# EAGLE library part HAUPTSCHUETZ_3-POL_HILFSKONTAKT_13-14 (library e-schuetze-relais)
Hauptschütz 3-pol. mit Hilfskontakt-Schließer
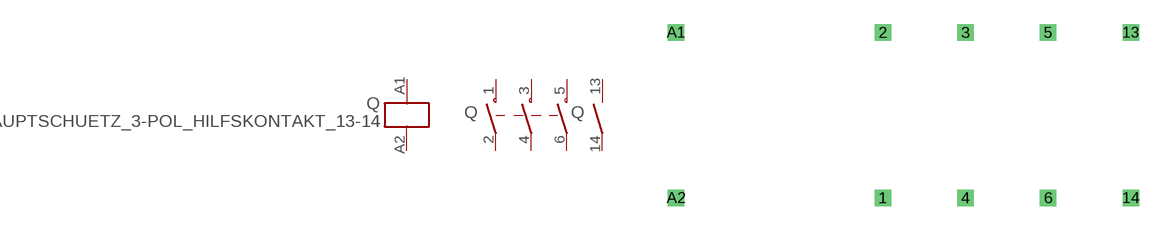
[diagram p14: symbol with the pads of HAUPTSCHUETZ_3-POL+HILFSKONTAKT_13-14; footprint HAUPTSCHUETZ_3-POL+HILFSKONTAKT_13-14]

Designator prefix Q; gates 1=SPULE 3=SCHLIESSER G$1=SCHLIESSER_HAUPTSCHUETZ_3-POL

## HAUPTSCHUETZ_3-POL_HILFSKONTAKT_13-14  [HAUPTSCHUETZ_3-POL+HILFSKONTAKT_13-14]
1  G$1:1  pas
2  G$1:2  pas
3  G$1:3  pas
4  G$1:4  pas
5  G$1:5  pas
6  G$1:6  pas
13  3:3  pas
14  3:4  pas
A1  1:A1  in
A2  1:A2  in

## Footprint HAUPTSCHUETZ_3-POL+HILFSKONTAKT_13-14 (pad centres in mm)
Dummy
drill 0.5 pad 1 square: 1 2.54,-7.62; 2 2.54,2.54; 3 7.62,2.54; 4 7.62,-7.62; 5 12.7,2.54; 6 12.7,-7.62; 13 17.78,2.54; 14 17.78,-7.62; A1 -10.16,2.54; A2 -10.16,-7.62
